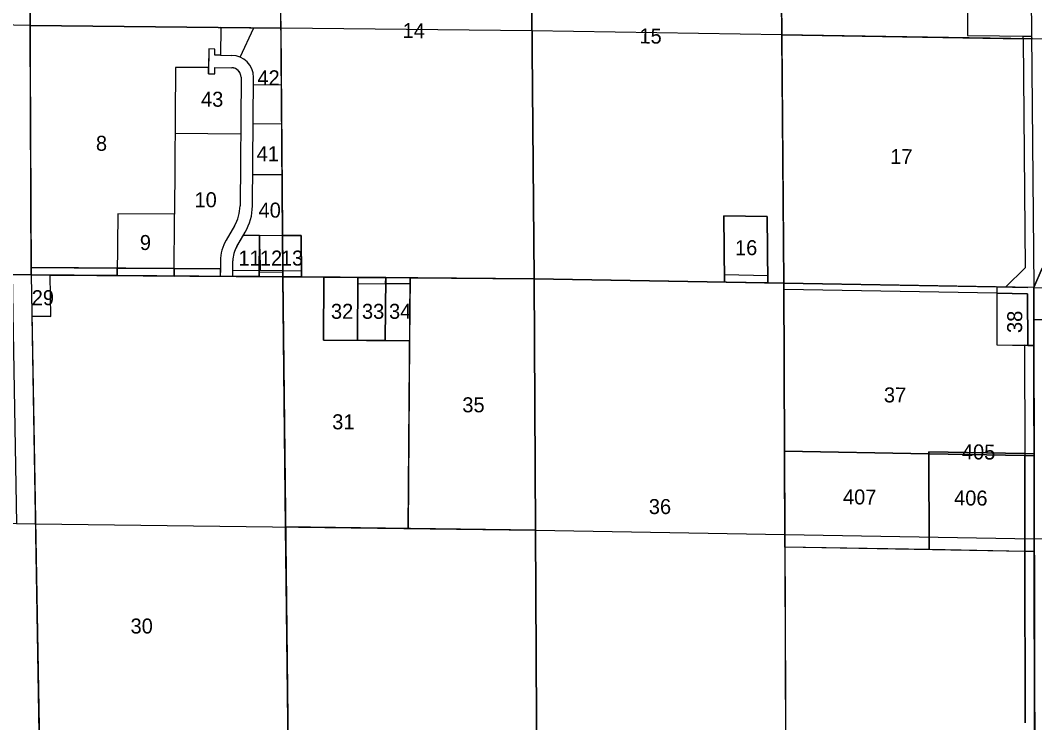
# Model space of a CAD drawing. Extents: x 582596 to 627039, y 145946 to 197316.
# Drawn here: x 599237 to 604634, y 167917 to 171651 of the extents above; entities that cross this region are included whole.
import ezdxf

# ---------------------------------------------------------------- set-up
doc = ezdxf.new("R2010")
doc.units = 0
for name, color, linetype in [('BNDRY', 7, 'Continuous'), ('Defpoints 2', 7, 'Continuous'), ('E_RW_Existing', 7, 'Continuous'), ('E_RW_SixteenthLine', 7, 'Continuous'), ('P_MISC_NoPlot', 7, 'Continuous'), ('P_RW_PropertyLine', 7, 'Continuous'), ('P_RW_SectionLine', 7, 'Continuous'), ('ROW', 7, 'Continuous'), ('SECTION', 7, 'Continuous')]:
    doc.layers.add(name, color=color, linetype=linetype)

# ---------------------------------------------------------------- blocks, each defined once
blk = doc.blocks.new('A$C04636ABF')
at = {"layer": 'BNDRY'}
blk.add_line((1004.7, 57.7), (-1.2, 40), dxfattribs=at)
for points in [[(0, 0), (-40.4, 1325.5), (974.1, 1340.2), (976.7, 1192.5), (946.8, 1192), (946.2, 1225), (913.2, 1224.4), (915.5, 1092.4), (948.5, 1093), (947.9, 1126), (1037.9, 1127.6)], [(1088.8, 1078.5), (1100.8, 395.2)], [(1074.1, 288), (1031.5, 211)], [(1004, 100.3), (1005.4, 17.7), (0, 0)]]:
    blk.add_lwpolyline(points, dxfattribs=at)
for centre, radius, start, end in [((1038.8, 1077.6), 50, 1.0097, 91.0097), ((887.5, 391.4), 213.3, 331.004, 1.0154), ((1223.5, 104.6), 219.6, 151.0065, 181.1088)]:
    blk.add_arc(centre, radius, start, end, dxfattribs=at)
at = {"layer": 'ROW'}
for p, q in [((1081.3, 1185.5), (1149.8, 1342.7)), ((1294.8, 1344.8), (1336.4, 56.6)), ((976.7, 1192.5), (1036.7, 1193.6)), ((1166.8, 396.3), (1154.8, 1079.6)), ((1155.4, 1041.6), (1304.5, 1044.2)), ((1311.2, 835.3), (1159.1, 832.6)), ((1320, 564.8), (1163.9, 562.1)), ((1089.2, 179), (1131.9, 256)), ((1122.9, 239.8), (1330.4, 243.5)), ((1212, 167.6), (1216.3, 54.4)), ((1070.9, 51.9), (1070, 101.9)), ((1070.9, 51.9), (1336.4, 56.6))]:
    blk.add_line(p, q, dxfattribs=at)
for centre, radius, start, end in [((1038.8, 1077.6), 116, 1.0097, 91.0097), ((887.5, 391.4), 279.3, 331.0097, 1.0097), ((1223.5, 104.6), 153.6, 151.0097, 181.1172)]:
    blk.add_arc(centre, radius, start, end, dxfattribs=at)
at = {"layer": 'SECTION'}
blk.add_line((1294.8, 1344.8), (974.1, 1340.2), dxfattribs=at)

msp = doc.modelspace()

# ---------------------------------------------------------------- linework, layer by layer
at = {"layer": 'Defpoints'}
for p, q in [((600367.1, 170289.7), (600301.1, 170290.2)), ((604629.1, 170230.1), (604479.4, 170232.8)), ((604633.8, 167557.8), (604629.4, 170060)), ((604629.4, 170060), (604629.6, 169922.7)), ((604580.7, 169348.3), (604630.7, 169347.4))]:
    msp.add_line(p, q, dxfattribs=at)
msp.add_lwpolyline([(604583, 168215.8), (604583, 168215.8)], dxfattribs=at)
at = {"layer": 'E_RW_Existing'}
for points in [[(604617.6, 171566.5), (604617.7, 171552.8), (604572.7, 171553.5), (604572.6, 171567.1)], [(599295.6, 170297.8), (599295.4, 170337.8), (599752.8, 170334.3), (599752.5, 170294.3)], [(599752.8, 170334.3), (600055.2, 170332), (600054.9, 170292), (599752.5, 170294.3)], [(600055.2, 170332), (600301.4, 170330.2), (600301.1, 170290.2), (600054.9, 170292)], [(600367.4, 170322.7), (600507.4, 170321.6), (600507.1, 170288.6), (600367.1, 170289.7)], [(600507.3, 170313.3), (600633, 170312.4), (600633.2, 170287.6), (600507.1, 170288.6)], [(600633.2, 170287.6), (600633, 170320.6), (600732.9, 170319.9), (600733.2, 170286.9)], [(601033.2, 170284.6), (601032.9, 170251.6), (601180.6, 170250.5), (601180.8, 170283.5)], [(601180.8, 170283.5), (601310.8, 170282.5), (601310.6, 170249.5), (601180.6, 170250.5)], [(603213.6, 170295.4), (603214, 170255.4), (602983.6, 170259.5), (602983.2, 170299.5)], [(604432.4, 170233.7), (604432.5, 170200.6), (603300.1, 170220.8), (603300, 170253.8)], [(604580.7, 169348.3), (604630.7, 169347.4), (604629.6, 169922.7), (604579.6, 169923.6)], [(604630.7, 169337.4), (604630.7, 169347.4), (604580.7, 169348.3), (604580.7, 169338.3)], [(604631.6, 168827.4), (604581.6, 168828.3), (604580.7, 169338.3), (604630.7, 169337.4)]]:
    msp.add_lwpolyline(points, close=True, dxfattribs=at)
for points in [[(604629.1, 170230.1), (604432.4, 170233.7), (604432.5, 170200.6), (604596.2, 170197.7), (604596.6, 169923.3), (604629.6, 169922.7), (604629.4, 170060)], [(604629.4, 170060), (604629.1, 170230.1)], [(604629.4, 170060), (604633.8, 167557.8)], [(604633.8, 167557.8), (604631.6, 168827.4), (604581.6, 168828.3), (604583.2, 167917.4)]]:
    msp.add_lwpolyline(points, dxfattribs=at)
at = {"layer": 'E_RW_SixteenthLine'}
for p, q in [((600633.2, 170287.6), (600614.4, 172931.3)), ((603276.7, 172894), (603300, 170253.8)), ((599288.6, 171623.9), (596652.4, 171670.1)), ((601958.9, 171595), (599288.6, 171623.9)), ((604617.7, 171552.8), (601958.9, 171595)), ((605943, 171523.9), (604617.7, 171552.8)), ((600663.2, 167628.3), (600633.2, 170287.6)), ((603300, 170253.8), (603309.4, 167581.4)), ((596678.4, 169015.7), (599318.5, 168974.7)), ((599318.5, 168974.7), (601977.9, 168941.2)), ((601977.9, 168941.2), (604631.5, 168894)), ((605958.9, 168865.5), (604631.5, 168894))]:
    msp.add_line(p, q, dxfattribs=at)
at = {"layer": 'P_MISC_NoPlot'}
for points in [[(606993.6, 160308.3), (600102.2, 147849.8), (582596.4, 147849.8), (584141, 197316), (605971.8, 196079.3), (609781.9, 181857.8), (607212.6, 178117.5), (605887.7, 178149.4), (605896.2, 176823.3), (605904.6, 175497.2), (605914.1, 174173.8), (605923.5, 172850.3), (605943, 171523.9), (604673.2, 170334), (604629.1, 170230.1), (604629.4, 170060), (605962, 170045), (605958.9, 168865.5), (605954.8, 167533.5), (604633.8, 167557.8), (604638.5, 164918.1), (606975.2, 164878.2), (606986.2, 162297)], [(606993.6, 160308.3), (600102.2, 147849.8), (582596.4, 147849.8), (584141, 197316), (605971.8, 196079.3), (609781.9, 181857.8), (607212.6, 178117.5), (605887.7, 178149.4), (605896.2, 176823.3), (605904.6, 175497.2), (605914.1, 174173.8), (605923.5, 172850.3), (605943, 171523.9), (604673.2, 170334), (604629.1, 170230.1), (604629.4, 170060), (605962, 170045), (605958.9, 168865.5), (605954.8, 167533.5), (604633.8, 167557.8), (604638.5, 164918.1), (606975.2, 164878.2), (606986.2, 162297)], [(606993.6, 160308.3), (600102.2, 147849.8), (582596.4, 147849.8), (584141, 197316), (605971.8, 196079.3), (609781.9, 181857.8), (607212.6, 178117.5), (605887.7, 178149.4), (605896.2, 176823.3), (605904.6, 175497.2), (605914.1, 174173.8), (605923.5, 172850.3), (605943, 171523.9), (604673.2, 170334), (604629.1, 170230.1), (604629.4, 170060), (605962, 170045), (605958.9, 168865.5), (605954.8, 167533.5), (604633.8, 167557.8), (604638.5, 164918.1), (606975.2, 164878.2), (606986.2, 162297)], [(606996.1, 159645.4), (606986.2, 162297), (606975.2, 164878.2), (604638.5, 164918.1), (604633.8, 167557.8), (605954.8, 167533.5), (605962, 170045), (604629.4, 170060), (604629.1, 170230.1), (604673.2, 170334), (605943, 171523.9), (605923.5, 172850.3), (605914.1, 174173.8), (605904.6, 175497.2), (605896.2, 176823.3), (605887.7, 178149.4), (607212.6, 178117.5), (607212.6, 178117.5), (627039.4, 170600.9), (626501.4, 158385.8), (609890.9, 158385.8), (607772.6, 159126.1)]]:
    msp.add_lwpolyline(points, close=True, dxfattribs=at)
at = {"layer": 'P_RW_PropertyLine'}
for p, q in [((600238.3, 171366.8), (600238.6, 171399.8)), ((600238.3, 171366.8), (600271.3, 171366.5)), ((600271.3, 171366.5), (600271.6, 171399.5)), ((600271.6, 171399.5), (600361.6, 171398.8)), ((600411.2, 171348.5), (600406, 170665.1)), ((600472, 170664.6), (600477.2, 171348)), ((600627.4, 171099.8), (600475.3, 171100.9)), ((600060.7, 171051.1), (600408.9, 171048.5)), ((600629.4, 170829.2), (600473.3, 170830.4)), ((600376.6, 170558.6), (600332, 170482.7)), ((600388.9, 170449.3), (600433.5, 170525.2)), ((600388.9, 170449.3), (600424.1, 170509.2)), ((600424.1, 170509.2), (600631.7, 170507.7)), ((600424.1, 170509.2), (600508.8, 170508.6)), ((600508.8, 170508.6), (600507.1, 170288.6)), ((600507.1, 170288.6), (600508.8, 170508.6)), ((600508.8, 170508.6), (600630.3, 170507.7)), ((600630.3, 170507.7), (600633.2, 170287.6)), ((600632, 170457.6), (600631.6, 170507.8)), ((600631.6, 170507.8), (600731.6, 170507)), ((600731.6, 170507), (600733.2, 170286.9)), ((600632, 170457.6), (600633.2, 170287.6)), ((600301.8, 170372.8), (600301.1, 170290.2)), ((600367.4, 170322.7), (600367.8, 170372.7)), ((599195.6, 170299.4), (599295.6, 170297.8)), ((599295.6, 170297.8), (599395.6, 170297)), ((600301.1, 170290.2), (599295.6, 170297.8)), ((599399.4, 170077), (599395.6, 170297)), ((600301.1, 170290.2), (600054.9, 170292)), ((600507.1, 170288.6), (600367.1, 170289.7)), ((600633.1, 170287.6), (600507.1, 170288.6)), ((600733.2, 170286.9), (600633.2, 170287.6)), ((601310.8, 170282.5), (601970.8, 170277.5)), ((604433, 170233.6), (604596.7, 170230.7)), ((604628.3, 170197.2), (604629.2, 170197.1)), ((599399.4, 170077), (599299.4, 170077.8)), ((601977.9, 168941.2), (600648.2, 168958))]:
    msp.add_line(p, q, dxfattribs=at)
for points in [[(597961, 172974.2), (599281.7, 172950), (599295.6, 170297.8), (597980, 170319.8)], [(599281.7, 172950), (599288.6, 171623.9), (600623.8, 171609.5), (600614.4, 172931.3)], [(601947.1, 172912.5), (601970.8, 170277.5), (600733.2, 170286.9), (600731.6, 170507), (600631.6, 170507.8), (600614.4, 172931.3)], [(601947.1, 172912.5), (603276.7, 172894), (603300, 170253.8), (603214, 170255.4), (603210.9, 170607.7), (602980.5, 170611.8), (602983.6, 170259.5), (601970.8, 170277.5)], [(604561.4, 172875), (604569.8, 171887.4), (604273.9, 171892.1), (604276.6, 171571), (604617.6, 171566.5), (604617.7, 171552.8), (603288.3, 171573.9), (603276.7, 172894)], [(599752.5, 170294.3), (599295.6, 170297.8), (599288.6, 171623.9), (600303.2, 171612.9), (600302.1, 171465.3), (600272.1, 171465.5), (600272.3, 171498.5), (600239.3, 171498.8), (600238.6, 171399.8), (600063.3, 171401.1), (600057.4, 170620.1), (599755, 170622.4)], [(603300, 170253.8), (603288.3, 171573.9), (604572.7, 171553.5), (604583.2, 170335.9), (604479.1, 170232.8)], [(602983.6, 170259.5), (602980.5, 170611.8), (603210.9, 170607.7), (603214, 170255.4)], [(599295.6, 170297.8), (599341.4, 167651.7), (598016.8, 167670.6), (597998.5, 168995.3), (599218.6, 168976.3), (599195.6, 170299.4)], [(599341.4, 167651.7), (599299.4, 170077.8), (599399.4, 170077), (599395.6, 170297), (600633.2, 170287.6), (600663.2, 167628.3)], [(600633.2, 170287.6), (600851.9, 170286), (600849.3, 169951.7), (601308.3, 169947.5), (601300.7, 168949.7), (600648.2, 168958)], [(600851.9, 170286), (601033.2, 170284.6), (601030.6, 169949.6), (600849.3, 169951.7)], [(601033.2, 170284.6), (601180.8, 170283.5), (601178.3, 169948.5), (601030.6, 169949.6)], [(601310.8, 170282.5), (601308.3, 169947.5), (601178.3, 169948.5), (601180.8, 170283.5)], [(601970.8, 170277.5), (601977.9, 168941.2), (601300.7, 168949.7), (601310.8, 170282.5)], [(601970.8, 170277.5), (603300, 170253.8), (603309.4, 167581.4), (601985, 167604.9)], [(604432.4, 170233.7), (604433, 169926.2), (604579.6, 169923.6), (604580.7, 169348.3), (604070.7, 169357.4), (604070.8, 169347.4), (603303.1, 169361.1), (603300, 170253.8)], [(604433, 169926.2), (604596.6, 169923.3), (604596.2, 170197.7), (604432.5, 170200.6)], [(604070.8, 169347.4), (604071.7, 168837.4), (603304.9, 168851.1), (603303.1, 169361.1)], [(604580.7, 169338.3), (604070.8, 169347.4), (604070.7, 169357.4), (604580.7, 169348.3)], [(604580.7, 169338.3), (604581.6, 168828.3), (604071.7, 168837.4), (604070.8, 169347.4)], [(601985, 167604.9), (600663.2, 167628.3), (600648.2, 168958), (601977.9, 168941.2)]]:
    msp.add_lwpolyline(points, close=True, dxfattribs=at)
for points in [[(599752.5, 170294.3), (600054.9, 170292), (600057.4, 170620.1), (599755, 170622.4), (599752.5, 170294.3)], [(604581.6, 168828.3), (603304.9, 168851.1), (603309.4, 167581.4), (603312.5, 166718.2), (604476.1, 166694), (604539.9, 167207.1)], [(604583.2, 167917.4), (604581.6, 168828.3)]]:
    msp.add_lwpolyline(points, dxfattribs=at)
for centre, radius, start, end in [((600361.2, 171348.8), 116, 359.5658, 89.5658), ((600361.2, 171348.8), 50, 359.5658, 89.5658), ((600192.7, 170666.7), 213.3, 329.5601, 359.5716), ((600192.7, 170666.7), 279.3, 329.5658, 359.5658), ((600521.4, 170371.5), 219.6, 149.5626, 179.6649), ((600521.4, 170371.5), 153.6, 149.5658, 179.6733), ((600521.4, 170371.5), 153.6, 149.5662, 179.5658)]:
    msp.add_arc(centre, radius, start, end, dxfattribs=at)
at = {"layer": 'P_RW_SectionLine'}
for p, q in [((599281.7, 172950), (599295.6, 170297.8)), ((601947.1, 172912.5), (601970.8, 170277.5)), ((604606.3, 172875.4), (604629.1, 170230.1)), ((599295.6, 170297.8), (596664.4, 170341.8)), ((601970.8, 170277.5), (599295.6, 170297.8)), ((599295.6, 170297.8), (599341.4, 167651.7)), ((604629.1, 170230.1), (601970.8, 170277.5)), ((601970.8, 170277.5), (601985, 167604.9)), ((604629.4, 170060), (604629.1, 170230.1)), ((604629.1, 170230.1), (607295.7, 170164.8)), ((604633.8, 167557.8), (604629.4, 170060))]:
    msp.add_line(p, q, dxfattribs=at)

# ---------------------------------------------------------------- block references
at = {"layer": 'P_RW_PropertyLine', "rotation": -1.443738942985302}
msp.add_blockref('A$C04636ABF', (599295.6, 170297.8), dxfattribs=at)

# ---------------------------------------------------------------- texts
at = {"layer": 'Defpoints 2'}
for s, rotation, p in [('14', 359.5042, (601270.6, 171557)), ('15', 359.5042, (602530.6, 171528.3)), ('17', 359.5042, (603865, 170887.4)), ('38', 89.5072, (604566.6, 169988.6)), ('37', 359.5042, (603831.2, 169620.3)), ('405', 359.5042, (604246.1, 169317.7)), ('407', 359.5042, (603613.5, 169078.4)), ('406', 359.5042, (604204.6, 169072.9))]:
    msp.add_text(s, height=79.68, rotation=rotation, dxfattribs=at).set_placement(p)
for s, height, p in [('42', 79.68, (600498.4, 171305.6)), ('43', 79.68, (600198.5, 171191.9)), ('8', 79.7, (599639.3, 170957.5)), ('41', 79.68, (600494.3, 170902.4)), ('10', 79.68, (600163.7, 170657.5)), ('40', 79.68, (600504.5, 170602.4)), ('9', 79.7, (599873, 170430.1)), ('16', 79.68, (603039.2, 170402.7)), ('11', 79.68, (600397.3, 170347.4)), ('12', 79.68, (600511.7, 170347.4)), ('13', 79.68, (600623.5, 170347.4)), ('29', 79.68, (599297.8, 170136.9)), ('32', 79.68, (600889.7, 170064.4)), ('33', 79.68, (601054.7, 170064.4)), ('34', 79.68, (601198.7, 170064.4)), ('35', 79.68, (601588.7, 169567.4)), ('31', 79.68, (600896.5, 169477)), ('36', 79.68, (602580.8, 169026.5)), ('30', 79.68, (599823.5, 168391.5))]:
    msp.add_text(s, height=height, dxfattribs=at).set_placement(p)

doc.saveas('drawing.dxf')
